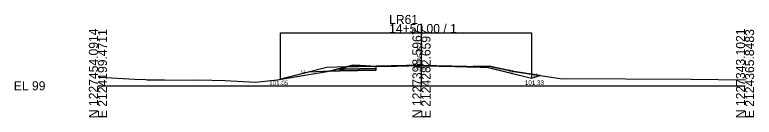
# Model space of a CAD drawing. Extents: x 2121193 to 2127979, y 1225108 to 1234639.
# Drawn here: x 2127750.9 to 2127979.4, y 1229607.5 to 1229639.1 of the extents above; entities that cross this region are included whole.
import ezdxf

# ---------------------------------------------------------------- set-up
doc = ezdxf.new("R2010")
doc.units = 0
for name, color, linetype in [('XS_CELL', 7, 'Continuous'), ('XS_M_DITCH', 7, 'Continuous'), ('XS_M_SHAPES_EARTHWORK', 7, 'Continuous'), ('XS_P_FINISHED_GRADE', 7, 'Continuous'), ('XS_P_FINISHED_GRADE_ELEV_TX', 7, 'Continuous'), ('XS_P_SUBGRADE_GRANULAR', 7, 'Continuous'), ('XS_P_SUBGRADE_LEVELING', 7, 'Continuous'), ('XS_P_SUBGRADE_PAVEMENT', 7, 'Continuous'), ('XS_P_TX_DCH', 7, 'Continuous'), ('XS_P_TX_FS_BS', 7, 'Continuous'), ('XS_X_GROUND', 7, 'Continuous'), ('XS_X_GROUND_TX', 7, 'Continuous')]:
    doc.layers.add(name, color=color, linetype=linetype)

msp = doc.modelspace()

# ---------------------------------------------------------------- linework, layer by layer
at = {"layer": 'XS_CELL'}
for p, q in [((2127876.61, 1229617.21), (2127876.61, 1229636.29)), ((2127776.61, 1229617.21), (2127876.61, 1229617.21)), ((2127876.61, 1229617.21), (2127976.61, 1229617.21))]:
    msp.add_line(p, q, dxfattribs=at)
at = {"layer": 'XS_M_DITCH'}
for p, q in [((2127833.01, 1229619.26), (2127833.01, 1229633.56)), ((2127833.01, 1229633.56), (2127910.61, 1229633.56)), ((2127910.61, 1229633.56), (2127910.61, 1229619.54))]:
    msp.add_line(p, q, dxfattribs=at)
at = {"layer": 'XS_M_SHAPES_EARTHWORK'}
for p, q in [((2127853.31, 1229623.04), (2127848.63, 1229621.81)), ((2127851.39, 1229622.35), (2127852.56, 1229622.37)), ((2127852.56, 1229622.37), (2127851.39, 1229622.35)), ((2127851.39, 1229621.85), (2127851.39, 1229622.35)), ((2127851.39, 1229622.35), (2127851.39, 1229621.85)), ((2127851.39, 1229621.85), (2127862.61, 1229622.07)), ((2127852.56, 1229622.37), (2127852.71, 1229622.62)), ((2127852.71, 1229622.62), (2127852.56, 1229622.37)), ((2127852.71, 1229622.62), (2127852.56, 1229622.37)), ((2127862.61, 1229622.57), (2127852.56, 1229622.37)), ((2127852.56, 1229622.37), (2127862.61, 1229622.57)), ((2127852.56, 1229622.37), (2127862.61, 1229622.57)), ((2127852.71, 1229622.62), (2127853.31, 1229623.04)), ((2127853.31, 1229623.04), (2127852.71, 1229622.62)), ((2127853.31, 1229623.04), (2127852.71, 1229622.62)), ((2127853.52, 1229623.1), (2127853.31, 1229623.04)), ((2127853.52, 1229623.1), (2127853.31, 1229623.04)), ((2127855.31, 1229623.57), (2127853.52, 1229623.1)), ((2127853.52, 1229623.1), (2127861, 1229623.25)), ((2127861, 1229623.25), (2127853.52, 1229623.1)), ((2127861, 1229623.25), (2127853.52, 1229623.1)), ((2127857.64, 1229623.45), (2127855.31, 1229623.57)), ((2127861, 1229623.25), (2127857.64, 1229623.45)), ((2127862.2, 1229623.18), (2127861, 1229623.25)), ((2127862.2, 1229623.18), (2127861, 1229623.25)), ((2127862.61, 1229623.18), (2127862.2, 1229623.18)), ((2127862.61, 1229623.18), (2127862.2, 1229623.18)), ((2127862.61, 1229623.15), (2127862.61, 1229623.18)), ((2127862.61, 1229622.57), (2127862.61, 1229623.15)), ((2127862.61, 1229622.07), (2127862.61, 1229622.57)), ((2127890.68, 1229623.15), (2127890.68, 1229623.03)), ((2127892.15, 1229623.09), (2127890.68, 1229623.15)), ((2127890.68, 1229623.03), (2127890.82, 1229623.02)), ((2127890.82, 1229623.02), (2127892.15, 1229623.09)), ((2127892.6, 1229623.12), (2127892.15, 1229623.09)), ((2127892.15, 1229623.09), (2127897.2, 1229622.89)), ((2127893.62, 1229623.16), (2127892.6, 1229623.12)), ((2127897.53, 1229623.31), (2127893.62, 1229623.16)), ((2127896.61, 1229623.04), (2127893.62, 1229623.16)), ((2127893.62, 1229623.16), (2127896.61, 1229623.04)), ((2127897.2, 1229622.89), (2127896.61, 1229623.04)), ((2127905.14, 1229621.67), (2127897.53, 1229623.31)), ((2127833.01, 1229619.26), (2127848.03, 1229621.71)), ((2127841.82, 1229621.46), (2127833.01, 1229619.26)), ((2127848.03, 1229621.71), (2127841.82, 1229621.46)), ((2127848.03, 1229621.71), (2127851.39, 1229621.85)), ((2127848.63, 1229621.81), (2127848.03, 1229621.71)), ((2127913.26, 1229620.42), (2127905.14, 1229621.67)), ((2127910.61, 1229619.54), (2127913.26, 1229620.42))]:
    msp.add_line(p, q, dxfattribs=at)
for points in [[(2127862.61, 1229622.57), (2127862.61, 1229623.15), (2127862.61, 1229623.18)], [(2127896.61, 1229623.04), (2127897.2, 1229622.89), (2127910.61, 1229619.54)]]:
    msp.add_lwpolyline(points, dxfattribs=at)
at = {"layer": 'XS_P_FINISHED_GRADE'}
for p, q in [((2127847.39, 1229622.85), (2127833.01, 1229619.26)), ((2127853.39, 1229623.09), (2127847.39, 1229622.85)), ((2127862.61, 1229623.28), (2127853.39, 1229623.09)), ((2127876.61, 1229623.56), (2127862.61, 1229623.28)), ((2127876.61, 1229623.56), (2127890.61, 1229623.28)), ((2127890.61, 1229623.28), (2127896.61, 1229623.04)), ((2127896.61, 1229623.04), (2127910.61, 1229619.54)), ((2127910.61, 1229619.54), (2127913.26, 1229620.42))]:
    msp.add_line(p, q, dxfattribs=at)
at = {"layer": 'XS_P_SUBGRADE_GRANULAR'}
for p, q in [((2127852.56, 1229622.37), (2127851.39, 1229622.35)), ((2127851.39, 1229621.85), (2127851.39, 1229622.35)), ((2127862.61, 1229622.07), (2127851.39, 1229621.85)), ((2127862.61, 1229622.07), (2127862.61, 1229622.57)), ((2127890.68, 1229623.15), (2127897.2, 1229622.89)), ((2127851.39, 1229621.85), (2127841.82, 1229621.46))]:
    msp.add_line(p, q, dxfattribs=at)
at = {"layer": 'XS_P_SUBGRADE_LEVELING'}
for p, q in [((2127877.12, 1229623.42), (2127887.06, 1229623.13)), ((2127887.06, 1229623.13), (2127890.68, 1229623.03))]:
    msp.add_line(p, q, dxfattribs=at)
at = {"layer": 'XS_P_SUBGRADE_PAVEMENT'}
for p, q in [((2127852.71, 1229622.62), (2127852.56, 1229622.37)), ((2127862.61, 1229622.57), (2127852.56, 1229622.37)), ((2127853.39, 1229623.09), (2127852.71, 1229622.62)), ((2127876.61, 1229623.43), (2127862.61, 1229623.15)), ((2127862.61, 1229622.57), (2127862.61, 1229623.15)), ((2127876.61, 1229623.43), (2127890.68, 1229623.15)), ((2127890.61, 1229623.28), (2127890.68, 1229623.15))]:
    msp.add_line(p, q, dxfattribs=at)
at = {"layer": 'XS_X_GROUND'}
for p, q in [((2127848.63, 1229621.81), (2127855.31, 1229623.57)), ((2127855.31, 1229623.57), (2127857.64, 1229623.45)), ((2127857.64, 1229623.45), (2127862.2, 1229623.18)), ((2127862.2, 1229623.18), (2127868.9, 1229623.29)), ((2127868.9, 1229623.29), (2127876.61, 1229623.44)), ((2127876.61, 1229623.44), (2127887.06, 1229623.13)), ((2127887.06, 1229623.13), (2127890.82, 1229623.02)), ((2127890.82, 1229623.02), (2127892.6, 1229623.12)), ((2127892.6, 1229623.12), (2127897.53, 1229623.31)), ((2127897.53, 1229623.31), (2127905.14, 1229621.67)), ((2127776.74, 1229619.87), (2127777.28, 1229619.86)), ((2127777.28, 1229619.86), (2127787.87, 1229619.24)), ((2127832.01, 1229619.1), (2127848.63, 1229621.81)), ((2127905.14, 1229621.67), (2127919.5, 1229619.46)), ((2127787.87, 1229619.24), (2127791.29, 1229619.16)), ((2127791.29, 1229619.16), (2127791.84, 1229619.09)), ((2127791.84, 1229619.09), (2127797.14, 1229619.1)), ((2127797.14, 1229619.1), (2127806.26, 1229618.99)), ((2127806.26, 1229618.99), (2127807.75, 1229619.04)), ((2127807.75, 1229619.04), (2127815.86, 1229618.8)), ((2127815.86, 1229618.8), (2127825.28, 1229618.3)), ((2127825.28, 1229618.3), (2127832.01, 1229619.1)), ((2127919.5, 1229619.46), (2127959.93, 1229619.26)), ((2127959.93, 1229619.26), (2127976.74, 1229619.1))]:
    msp.add_line(p, q, dxfattribs=at)

# ---------------------------------------------------------------- texts
at = {"layer": 'XS_CELL'}
for s, p in [('LR61', (2127866.61, 1229636.29)), ('14+50.00 / 1', (2127866.61, 1229633.49)), ('EL 99', (2127750.61, 1229615.81))]:
    msp.add_text(s, height=2.8, dxfattribs=at).set_placement(p)
for s, p in [('N 1227454.0914', (2127776.61, 1229607.21)), ('E 2124199.4711', (2127779.41, 1229607.21)), ('N 1227398.5967', (2127876.61, 1229607.21)), ('E 2124282.6597', (2127879.41, 1229607.21)), ('N 1227343.1021', (2127976.61, 1229607.21)), ('E 2124365.8483', (2127979.41, 1229607.21))]:
    msp.add_text(s, height=2.8, rotation=90, dxfattribs=at).set_placement(p)
at = {"layer": 'XS_P_FINISHED_GRADE_ELEV_TX'}
msp.add_text(' 105.35', height=1.25, rotation=90, dxfattribs=at).set_placement((2127876.61, 1229623.56))
at = {"layer": 'XS_P_TX_DCH'}
for s, p in [('101.05', (2127829.52, 1229617.42)), ('101.33', (2127908.56, 1229617.46))]:
    msp.add_text(s, height=1.4, dxfattribs=at).set_placement(p)
at = {"layer": 'XS_P_TX_FS_BS'}
for s, rotation, p in [('4:1', 14.0362, (2127839.36, 1229621.1)), ('4:1', 345.9638, (2127903.38, 1229621.6)), ('3:1', 18.4349, (2127911.21, 1229619.88))]:
    msp.add_text(s, height=0.8, rotation=rotation, dxfattribs=at).set_placement(p)
at = {"layer": 'XS_X_GROUND_TX'}
msp.add_text('105.23', height=1, dxfattribs=at).set_placement((2127874.18, 1229622.27))

doc.saveas('drawing.dxf')
